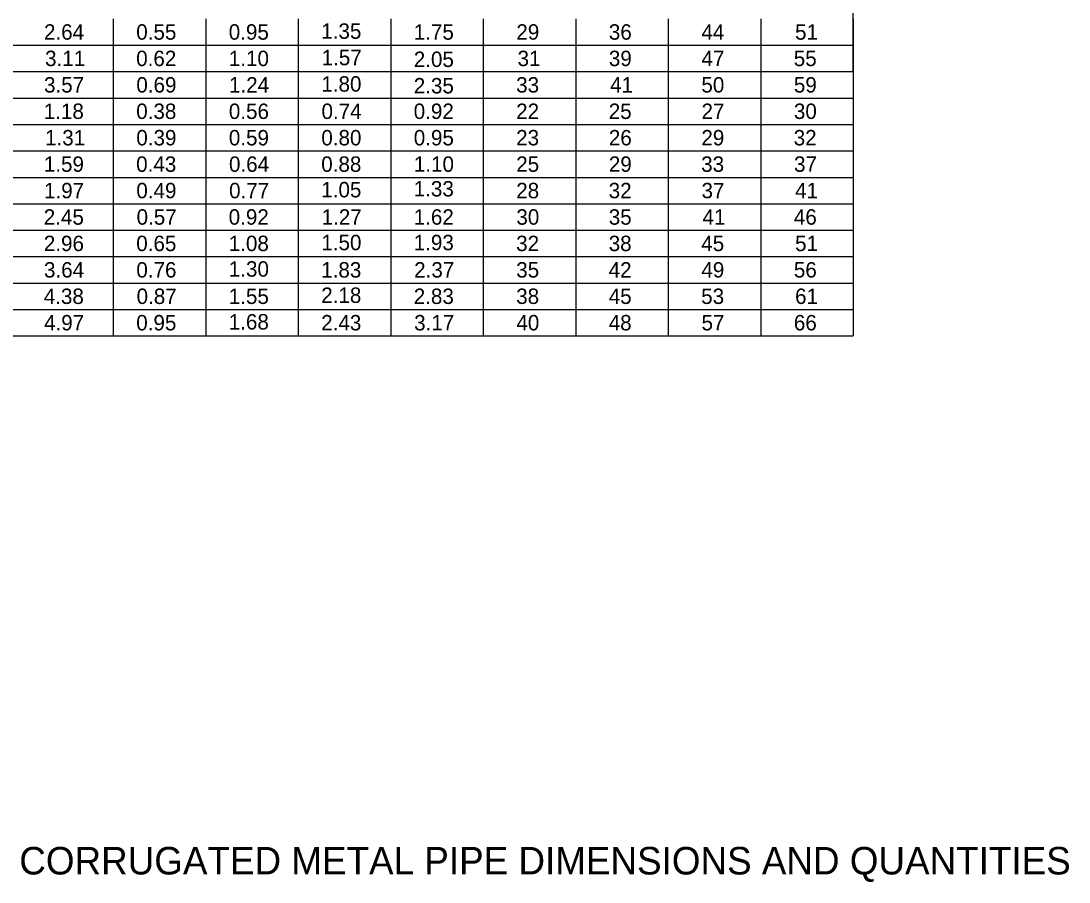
# Model space of a CAD drawing. Extents: x -1.3 to 14.4, y 0 to 7.8.
# Drawn here: x 9.681 to 14.439, y 0.01 to 3.92 of the extents above; entities that cross this region are included whole.
import ezdxf

# ---------------------------------------------------------------- set-up
doc = ezdxf.new("R2010")
doc.units = 0
doc.layers.add('Table', color=7, linetype='Continuous')
doc.layers.add('TextStructures', color=7, linetype='Continuous')

msp = doc.modelspace()

# ---------------------------------------------------------------- linework, layer by layer
at = {"layer": 'Table'}
for points in [[(13.46, 3.93), (13.46, 3.81), (13.46, 3.69), (13.46, 4.53)], [(10.1, 3.93), (10.1, 3.81), (10.1, 3.69), (10.1, 3.57), (10.1, 3.45), (10.1, 3.33), (10.1, 3.21), (10.1, 3.09), (10.1, 2.97), (10.1, 2.85), (10.1, 2.73), (10.1, 2.61), (10.1, 2.49)], [(10.52, 3.93), (10.52, 3.81), (10.52, 3.69), (10.52, 3.57), (10.52, 3.45), (10.52, 3.33), (10.52, 3.21), (10.52, 3.09), (10.52, 2.97), (10.52, 2.85), (10.52, 2.73), (10.52, 2.61), (10.52, 2.49)], [(10.94, 3.93), (10.94, 3.81), (10.94, 3.69), (10.94, 3.57), (10.94, 3.45), (10.94, 3.33), (10.94, 3.21), (10.94, 3.09), (10.94, 2.97), (10.94, 2.85), (10.94, 2.73), (10.94, 2.61), (10.94, 2.49)], [(11.36, 3.93), (11.36, 3.81), (11.36, 3.69), (11.36, 3.57), (11.36, 3.45), (11.36, 3.33), (11.36, 3.21), (11.36, 3.09), (11.36, 2.97), (11.36, 2.85), (11.36, 2.73), (11.36, 2.61), (11.36, 2.49)], [(11.78, 3.93), (11.78, 3.81), (11.78, 3.69), (11.78, 3.57), (11.78, 3.45), (11.78, 3.33), (11.78, 3.21), (11.78, 3.09), (11.78, 2.97), (11.78, 2.85), (11.78, 2.73), (11.78, 2.61), (11.78, 2.49)], [(12.2, 3.93), (12.2, 3.81), (12.2, 3.69), (12.2, 3.57), (12.2, 3.45), (12.2, 3.33), (12.2, 3.21), (12.2, 3.09), (12.2, 2.97), (12.2, 2.85), (12.2, 2.73), (12.2, 2.61), (12.2, 2.49)], [(12.62, 3.93), (12.62, 3.81), (12.62, 3.69), (12.62, 3.57), (12.62, 3.45), (12.62, 3.33), (12.62, 3.21), (12.62, 3.09), (12.62, 2.97), (12.62, 2.85), (12.62, 2.73), (12.62, 2.61), (12.62, 2.49)], [(13.04, 3.93), (13.04, 3.81), (13.04, 3.69), (13.04, 3.57), (13.04, 3.45), (13.04, 3.33), (13.04, 3.21), (13.04, 3.09), (13.04, 2.97), (13.04, 2.85), (13.04, 2.73), (13.04, 2.61), (13.04, 2.49)], [(13.46, 3.93), (13.46, 3.81), (13.46, 3.69), (13.46, 3.57), (13.46, 3.45), (13.46, 3.33), (13.46, 3.21), (13.46, 3.09), (13.46, 2.97), (13.46, 2.85), (13.46, 2.73), (13.46, 2.61), (13.46, 2.49)], [(6.38, 3.81), (6.8, 3.81), (7.22, 3.81), (7.64, 3.81), (8.06, 3.81), (8.42, 3.81), (8.84, 3.81), (9.26, 3.81), (9.68, 3.81), (10.1, 3.81), (10.52, 3.81), (10.94, 3.81), (11.36, 3.81), (11.78, 3.81), (12.2, 3.81), (12.62, 3.81), (13.04, 3.81), (13.46, 3.81)], [(6.38, 3.69), (6.8, 3.69), (7.22, 3.69), (7.64, 3.69), (8.06, 3.69), (8.42, 3.69), (8.84, 3.69), (9.26, 3.69), (9.68, 3.69), (10.1, 3.69), (10.52, 3.69), (10.94, 3.69), (11.36, 3.69), (11.78, 3.69), (12.2, 3.69), (12.62, 3.69), (13.04, 3.69), (13.46, 3.69)], [(6.38, 3.57), (6.8, 3.57), (7.22, 3.57), (7.64, 3.57), (8.06, 3.57), (8.42, 3.57), (8.84, 3.57), (9.26, 3.57), (9.68, 3.57), (10.1, 3.57), (10.52, 3.57), (10.94, 3.57), (11.36, 3.57), (11.78, 3.57), (12.2, 3.57), (12.62, 3.57), (13.04, 3.57), (13.46, 3.57)], [(6.38, 3.45), (6.8, 3.45), (7.22, 3.45), (7.64, 3.45), (8.06, 3.45), (8.42, 3.45), (8.84, 3.45), (9.26, 3.45), (9.68, 3.45), (10.1, 3.45), (10.52, 3.45), (10.94, 3.45), (11.36, 3.45), (11.78, 3.45), (12.2, 3.45), (12.62, 3.45), (13.04, 3.45), (13.46, 3.45)], [(6.38, 3.33), (6.8, 3.33), (7.22, 3.33), (7.64, 3.33), (8.06, 3.33), (8.42, 3.33), (8.84, 3.33), (9.26, 3.33), (9.68, 3.33), (10.1, 3.33), (10.52, 3.33), (10.94, 3.33), (11.36, 3.33), (11.78, 3.33), (12.2, 3.33), (12.62, 3.33), (13.04, 3.33), (13.46, 3.33)], [(6.38, 3.21), (6.8, 3.21), (7.22, 3.21), (7.64, 3.21), (8.06, 3.21), (8.42, 3.21), (8.84, 3.21), (9.26, 3.21), (9.68, 3.21), (10.1, 3.21), (10.52, 3.21), (10.94, 3.21), (11.36, 3.21), (11.78, 3.21), (12.2, 3.21), (12.62, 3.21), (13.04, 3.21), (13.46, 3.21)], [(6.38, 3.09), (6.8, 3.09), (7.22, 3.09), (7.64, 3.09), (8.06, 3.09), (8.42, 3.09), (8.84, 3.09), (9.26, 3.09), (9.68, 3.09), (10.1, 3.09), (10.52, 3.09), (10.94, 3.09), (11.36, 3.09), (11.78, 3.09), (12.2, 3.09), (12.62, 3.09), (13.04, 3.09), (13.46, 3.09)], [(6.38, 2.97), (6.8, 2.97), (7.22, 2.97), (7.64, 2.97), (8.06, 2.97), (8.42, 2.97), (8.84, 2.97), (9.26, 2.97), (9.68, 2.97), (10.1, 2.97), (10.52, 2.97), (10.94, 2.97), (11.36, 2.97), (11.78, 2.97), (12.2, 2.97), (12.62, 2.97), (13.04, 2.97), (13.46, 2.97)], [(6.38, 2.85), (6.8, 2.85), (7.22, 2.85), (7.64, 2.85), (8.06, 2.85), (8.42, 2.85), (8.84, 2.85), (9.26, 2.85), (9.68, 2.85), (10.1, 2.85), (10.52, 2.85), (10.94, 2.85), (11.36, 2.85), (11.78, 2.85), (12.2, 2.85), (12.62, 2.85), (13.04, 2.85), (13.46, 2.85)], [(6.38, 2.73), (6.8, 2.73), (7.22, 2.73), (7.64, 2.73), (8.06, 2.73), (8.42, 2.73), (8.84, 2.73), (9.26, 2.73), (9.68, 2.73), (10.1, 2.73), (10.52, 2.73), (10.94, 2.73), (11.36, 2.73), (11.78, 2.73), (12.2, 2.73), (12.62, 2.73), (13.04, 2.73), (13.46, 2.73)], [(6.38, 2.61), (6.8, 2.61), (7.22, 2.61), (7.64, 2.61), (8.06, 2.61), (8.42, 2.61), (8.84, 2.61), (9.26, 2.61), (9.68, 2.61), (10.1, 2.61), (10.52, 2.61), (10.94, 2.61), (11.36, 2.61), (11.78, 2.61), (12.2, 2.61), (12.62, 2.61), (13.04, 2.61), (13.46, 2.61)], [(6.38, 2.49), (6.8, 2.49), (7.22, 2.49), (7.64, 2.49), (8.06, 2.49), (8.42, 2.49), (8.84, 2.49), (9.26, 2.49), (9.68, 2.49), (10.1, 2.49), (10.52, 2.49), (10.94, 2.49), (11.36, 2.49), (11.78, 2.49), (12.2, 2.49), (12.62, 2.49), (13.04, 2.49), (13.46, 2.49)]]:
    msp.add_lwpolyline(points, dxfattribs=at)

# ---------------------------------------------------------------- texts
for s, p in [('2.64', (9.7854, 3.835)), ('29', (11.93, 3.835)), ('36', (12.35, 3.835)), ('44', (12.7706, 3.835)), ('51', (13.1955, 3.835)), ('3.11', (9.7903, 3.715)), ('31', (11.9355, 3.715)), ('39', (12.35, 3.715)), ('47', (12.7708, 3.715)), ('55', (13.1895, 3.715)), ('3.57', (9.7856, 3.595)), ('33', (11.9292, 3.595)), ('41', (12.3555, 3.595)), ('50', (12.7701, 3.595)), ('59', (13.19, 3.595)), ('1.18', (9.7842, 3.475)), ('22', (11.9292, 3.475)), ('25', (12.3495, 3.475)), ('27', (12.7708, 3.475)), ('30', (13.1901, 3.475)), ('1.31', (9.7903, 3.355)), ('23', (11.9292, 3.355)), ('26', (12.35, 3.355)), ('29', (12.77, 3.355)), ('32', (13.1892, 3.355)), ('1.59', (9.7847, 3.235)), ('25', (11.9295, 3.235)), ('29', (12.35, 3.235)), ('33', (12.7692, 3.235)), ('37', (13.1908, 3.235)), ('1.97', (9.7856, 3.115)), ('28', (11.9294, 3.115)), ('32', (12.3492, 3.115)), ('37', (12.7708, 3.115)), ('41', (13.1955, 3.115)), ('2.45', (9.7843, 2.995)), ('30', (11.9301, 2.995)), ('35', (12.3495, 2.995)), ('41', (12.7755, 2.995)), ('46', (13.19, 2.995)), ('2.96', (9.7847, 2.875)), ('32', (11.9292, 2.875)), ('38', (12.3494, 2.875)), ('45', (12.7695, 2.875)), ('51', (13.1955, 2.875)), ('3.64', (9.7854, 2.755)), ('35', (11.9295, 2.755)), ('42', (12.3492, 2.755)), ('49', (12.77, 2.755)), ('56', (13.19, 2.755)), ('4.38', (9.7842, 2.635)), ('38', (11.9294, 2.635)), ('45', (12.3495, 2.635)), ('53', (12.7692, 2.635)), ('61', (13.1955, 2.635)), ('4.97', (9.7856, 2.515)), ('40', (11.9301, 2.515)), ('48', (12.3494, 2.515)), ('57', (12.7708, 2.515)), ('66', (13.19, 2.515))]:
    msp.add_text(s, height=0.07, rotation=0, dxfattribs=at).set_placement(p)
for s, p in [('0.55', (10.2043, 3.835)), ('0.95', (10.6243, 3.835)), ('1.35', (11.0443, 3.839)), ('1.75', (11.4643, 3.835)), ('0.62', (10.204, 3.715)), ('1.10', (10.6246, 3.715)), ('1.57', (11.046, 3.719)), ('2.05', (11.4643, 3.711)), ('0.69', (10.2047, 3.595)), ('1.24', (10.6254, 3.595)), ('1.80', (11.0446, 3.599)), ('2.35', (11.4643, 3.591)), ('0.38', (10.2042, 3.475)), ('0.56', (10.6247, 3.475)), ('0.74', (11.0454, 3.475)), ('0.92', (11.464, 3.475)), ('0.39', (10.2047, 3.355)), ('0.59', (10.6247, 3.355)), ('0.80', (11.0446, 3.355)), ('0.95', (11.4643, 3.355)), ('0.43', (10.2039, 3.235)), ('0.64', (10.6254, 3.235)), ('0.88', (11.0442, 3.235)), ('1.10', (11.4646, 3.235)), ('1.05', (11.0443, 3.119)), ('1.33', (11.464, 3.1231)), ('0.49', (10.2047, 3.115)), ('0.77', (10.6259, 3.115)), ('0.57', (10.2059, 2.995)), ('0.92', (10.624, 2.995)), ('1.27', (11.0459, 2.995)), ('1.62', (11.464, 2.995)), ('0.65', (10.2043, 2.875)), ('1.08', (10.6242, 2.875)), ('1.50', (11.0446, 2.879)), ('1.93', (11.464, 2.879)), ('0.76', (10.2047, 2.755)), ('1.30', (10.6245, 2.759)), ('1.83', (11.044, 2.755)), ('2.37', (11.466, 2.755)), ('0.87', (10.2059, 2.635)), ('1.55', (10.6243, 2.635)), ('2.18', (11.0442, 2.6399)), ('2.83', (11.4641, 2.635)), ('0.95', (10.2043, 2.515)), ('1.68', (10.6242, 2.519)), ('2.43', (11.044, 2.515)), ('3.17', (11.466, 2.515))]:
    msp.add_text(s, height=0.07, dxfattribs=at).set_placement(p)
at = {"layer": 'TextStructures'}
msp.add_text('CORRUGATED METAL PIPE DIMENSIONS AND QUANTITIES', height=0.125, dxfattribs=at).set_placement((9.6733, 0.0447))

doc.saveas('drawing.dxf')
